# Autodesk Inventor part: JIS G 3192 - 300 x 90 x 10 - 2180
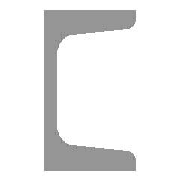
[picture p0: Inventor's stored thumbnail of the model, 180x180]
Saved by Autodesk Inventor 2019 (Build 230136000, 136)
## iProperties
_CCFamilyMember: 12
_CCFamilyDisplayName: JIS G 3192 - U 形熱間圧延鋼
_FrameMemberDoc: Frame Member File
_Version: 15.0.0
_GetPNFromCC: 1
Created: 2017-02
Part Number: JIS G 3192 - 300 x 90 x 10 - 2180
Material: 鋼、軟鋼
Description: U 形熱間圧延鋼
Document SubType Name: Modeling
Standard: JIS
Designer: shimont
Standard Revision: 2014
Standards Organization: JIS
Language: ja-JP
Size Designation: 300 x 90 x 10
Categories: <MemberInstance><Categories><Category DisplayName="形鋼" InternalName="089c4875-fa83-4c05-b084-43b9cc11f5ed" Mnemonic="GRDR"><CategoryParameter DisplayName="長さ単位ご
Stock Number: 300 x 90 x 10
Density: 7.85 g/cm^3
Appearance: 半つや出し
Mass: 95396.9 g
Surface Area: 19877.8 cm^2
Volume: 12152.5 cm^3
IsCustomPart: 1
G_L: 2180.000 mm
G_W: 90.000 mm
G_H: 300.000 mm
+56BA8A46-DE33-4272-95DB-061DA6D6BB4E+CUTDETAIL1: カット角度 90.00 deg
Author: shimont
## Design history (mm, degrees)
node "開始平面"
node "終了平面"
sketch "スケッチ"
  geometry: L1 (-23.4, 0)-(-23.4, 150); L2 (-23.4, 150)-(66.6, 150); L3 (66.6, 150)-(66.6, 146.705); L4 (57.928, 137.241)-(3.944, 132.518); L5 (-13.4, 113.59)-(-13.4, 0); L6 (-13.4, 0)-(-23.4, 0); L7 (26.6, 150)-(26.6, 134.5); L8 (66.6, 138)-(66.6, 134.5); L9 (66.6, 134.5)-(26.6, 134.5); L10 (0, 15)-(0, -27); L11 (-5.539, 0)-(16.007, 0); L12 (-23.4, 0)-(-23.4, -150); L13 (-23.4, -150)-(66.6, -150); L14 (66.6, -150)-(66.6, -146.705); L15 (57.928, -137.241)-(3.944, -132.518); L16 (-13.4, -113.59)-(-13.4, 0); L17 (0, 210)-(0, -210) reference; L18 (-41.768, 0)-(86.808, 0) reference; A1 r 19 centre (5.6, 113.59) between (3.944, 132.518) and (-13.4, 113.59); A2 r 19 centre (5.6, -113.59) between (-13.4, -113.59) and (3.944, -132.518); A3 r 9.5 centre (57.1, 146.705) between (57.928, 137.241) and (66.6, 146.705); A4 r 9.5 centre (57.1, -146.705) between (66.6, -146.705) and (57.928, -137.241); 5 further points
  constraints: 32 end point, 12 point on line, 8 point on circle, 8 tangent, 6 symmetric about line, 4 centre point, 4 parallel, 3 collinear, 3 perpendicular, 2 equal radius, 5 other
  dimensions: "d0" = 10 distance between parallel lines of L1 L5 (= G_T); "d1" = 150 distance between parallel lines of L6 L2 (= 0.5 x G_H); "d2" = 90 distance between parallel lines of L3 L1 (= G_W); "d3" = 15.5 distance of L2.end L8.end (= G_T1); "d4" = 40 distance of L7.start L2.end (= G_C); "d5" = 3.4996 distance of L8.start L8.end (computed from G_NG, G_C); "d23" = 19 radius of A1 (= G_IR); "d24" = 9.5 radius of A3 (= G_ER); "d25" = 23.4 distance between parallel lines of L10 L12 (= ey)
extrude "ボディ" new body sketch "スケッチ" stored distance "d6" = 2180 (= G_L); taper "d7" = 0 deg
node "Driven Length"
  sketch "Sketch3"
    geometry: L1 (0, 0)-(10, 0) reference
    constraints: 2 end point, 1 horizontal
  workplane "Work Plane3"
  sketch "Sketch4"
    geometry: L1 (-2, -90)-(12, -90) reference; L2 (-2, 2090)-(12, 2090) reference
    dimensions: "d29" = 2180 distance between parallel lines of L1 L2 (derived)
node "作業平面4"
feature "分割1"
node "作業平面5"
feature "分割2"
body "Solid1"
other parameters: "G_W" = 90 [user parameter; used in 1 equation term], "G_H" = 300 [user parameter; used in 1 equation term], "G_T" = 10 [user parameter; used in 1 equation term], "G_T1" = 15.5 [user parameter; used in 1 equation term], "G_NG" = 0.8749 [user parameter; used in 1 equation term], "G_ER" = 9.5 [user parameter; used in 1 equation term], "G_IR" = 19 [user parameter; used in 1 equation term], "G_C" = 40 [user parameter; used in 2 equation terms], "G_L" = 2180 (= d29) [user parameter; used in 1 equation term], "ey" = 23.4 [user parameter; used in 1 equation term], "d28" = 90 deg
